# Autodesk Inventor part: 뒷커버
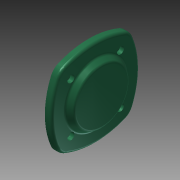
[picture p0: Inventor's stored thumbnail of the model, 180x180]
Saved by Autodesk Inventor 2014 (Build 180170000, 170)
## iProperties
Created: 2015-11
Part Number: 뒷커버
Material: Aluminum 6061
Document SubType Name: Modeling
Designer: mduedu
Density: 2.71 g/cm^3
Mass: 325.352 g
Surface Area: 247.583 cm^2
Volume: 120.056 cm^3
Appearance: Smooth - Dark Sea Green
Author: mduedu
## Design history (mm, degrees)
sketch "스케치1"
  geometry: L1 (50, 50)-(-50, 50); L2 (-50, 50)-(-50, -50); L3 (-50, -50)-(50, -50); L4 (50, -50)-(50, 50); L5 (0, 50)-(0, -50); L6 (50, 0)-(-50, 0); A1 r 90 centre (-40, 0) between (40.415, -40.415) and (40.415, 40.415); A2 r 90 centre (40, 0) between (-40.415, 40.415) and (-40.415, -40.415); A3 r 90 centre (0, -40) between (40.415, 40.415) and (-40.415, 40.415); A4 r 90 centre (0, 40) between (-40.415, -40.415) and (40.415, -40.415); 2 further points
  constraints: 12 end point, 8 point on circle, 5 midpoint, 4 centre point, 2 horizontal alignment, 2 parallel, 2 perpendicular, 2 symmetric about line, 2 tangent, 2 vertical alignment, 1 equal radius, 1 horizontal, 2 other
  dimensions: "d0" = 100 distance of L3.end L1.start; "d2" = 90 radius of A1
extrude "돌출1" new body sketch "스케치1" distance "d3" = 8; taper "d4" = 0 deg
sketch "스케치2"
  geometry: C1 r 35 at (0, 0); 1 further point
  constraints: 1 centre point, 1 coincident
  dimensions: "d5" = 70 diameter of C1
extrude "돌출2" join sketch "스케치2" distance "d6" = 7; taper "d7" = -30 deg
sketch "스케치3"
  geometry: L1 (0, 0)-(0, 40); L2 (0, 0)-(-28.284, 28.284); A1 r 40 centre (0, 0) between (0, 40) and (-28.284, 28.284); 2 further points
  constraints: 4 end point, 2 coincident, 2 point on circle, 1 centre point, 1 vertical
  dimensions: "d8" = 80 diameter of A1; "d9" = 45 deg angle of L1 L2
hole "구멍1" sketch "스케치3" at (-28.284, 28.284) diameter "d11" = 4.5; stored, may be unused: countersink angle "d15" = 90 deg, drill point angle "d17" = 118 deg; dims "d12" = 6, "d13" = 8, "d14" = 4.4, "d16" = 8
sketch "스케치4"
  geometry: C1 r 35 at (0, 0); 1 further point
  constraints: 1 centre point, 1 coincident
  dimensions: "d21" = 70 diameter of C1
extrude "돌출3" join sketch "스케치4" distance "d23" = 12; taper "d24" = 0 deg
hole "구멍2" diameter "d27" = 30; stored, may be unused: countersink angle "d31" = 90 deg, drill point angle "d33" = 0 deg; dims "d25" = 10, "d26" = 10, "d28" = 6, "d29" = 40, "d30" = 12, "d32" = 15
fillet "모깎기2" dims "d35" = 15
fillet "모깎기3" dims "d36" = 3
fillet "모깎기4" dims "d37" = 3
fillet "모깎기5" dims "d38" = 0.3
chamfer "모따기1" distance "d39" = 1; stored, may be unused: second distance "d40" = 2, angle "d41" = 45 deg
node "솔리드1"
pattern_circular "원형 패턴1" dims angle "d19" = 360 deg
